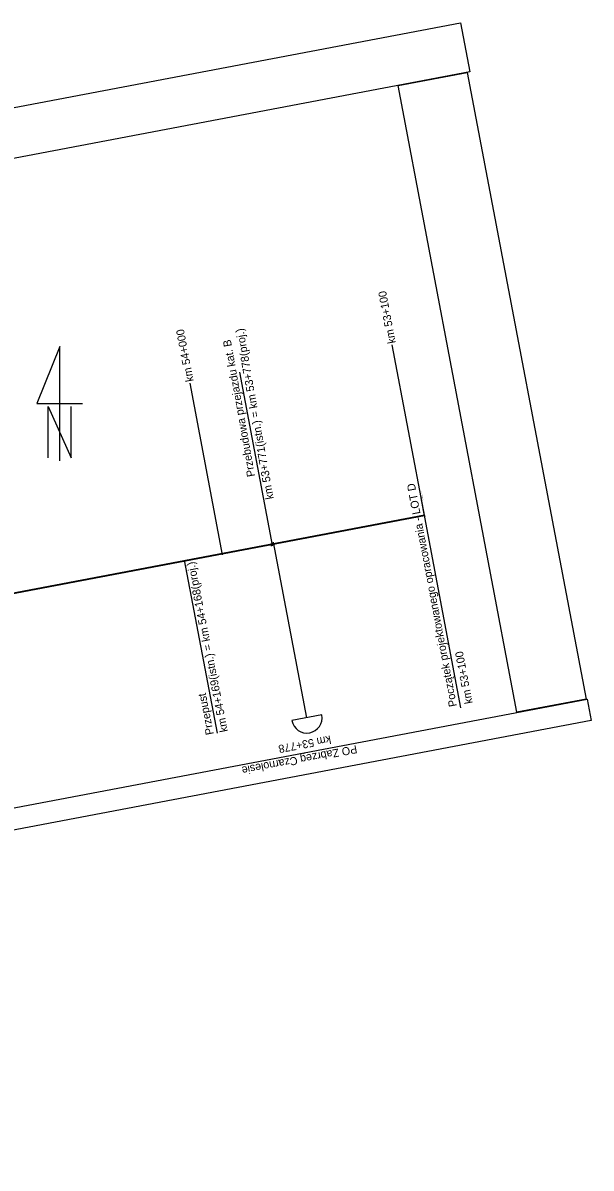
# Model space of a CAD drawing. Extents: x 6540402 to 6566579, y 5525343 to 5532423.
# Drawn here: x 6564093 to 6566579, y 5527416 to 5532423 of the extents above; entities that cross this region are included whole.
import ezdxf

# ---------------------------------------------------------------- set-up
doc = ezdxf.new("R2010")
doc.units = 0
for name, color, linetype in [('IR_default', 7, 'Continuous'), ('IR_ps_geometria', 7, 'Continuous'), ('TOR_PS_OPIS_T-hektometry projektowane', 7, 'Continuous'), ('TOR_PS_OPIS_T-opisy dodatkowe', 7, 'Continuous'), ('TOR_PS_OPIS_T-opisy glowne', 7, 'Continuous'), ('TOR_PS_P-płyty przejazdowe', 7, 'Continuous'), ('TOR_PS_T-tory projektowane', 7, 'Continuous'), ('TOR_RAMKI-ramka+tabelka 2', 7, 'Continuous')]:
    doc.layers.add(name, color=color, linetype=linetype)

msp = doc.modelspace()

# ---------------------------------------------------------------- linework, layer by layer
at = {"layer": 'DEFPOINTS'}
for points in [[(6566047.7, 5532208.3), (6558046.4, 5530690.8), (6558005.7, 5530905.3), (6566007, 5532422.8)], [(6566556.8, 5529465.9), (6566254.4, 5529408.5), (6565734.6, 5532148.9), (6566037, 5532206.3)], [(6566578.8, 5529372.7), (6556259.2, 5527415.6), (6556241.4, 5527509.5), (6566561, 5529466.6)]]:
    msp.add_lwpolyline(points, close=True, dxfattribs=at)
at = {"layer": 'IR_default'}
for p, q in [((6564204.3, 5530521), (6564204.3, 5530746)), ((6564204.3, 5530746), (6564304.3, 5530521)), ((6564304.3, 5530521), (6564304.3, 5530746))]:
    msp.add_line(p, q, dxfattribs=at)
msp.add_lwpolyline([(6564254.3, 5530508.5), (6564254.3, 5531008.5), (6564154.3, 5530758.5), (6564354.3, 5530758.5)], dxfattribs=at)
at = {"layer": 'IR_ps_geometria'}
msp.add_lwpolyline([(6565850.4, 5530267.1), (6565850.4, 5530266.9), (6565850.4, 5530266.9), (6565850.5, 5530266.9), (6565850.5, 5530266.9), (6565850.5, 5530266.9), (6565850.6, 5530266.9), (6565850.6, 5530266.8), (6565850.6, 5530266.8), (6565850.6, 5530266.8), (6565850.7, 5530266.8), (6565850.7, 5530266.8), (6565850.7, 5530266.7), (6565850.7, 5530266.7), (6565850.7, 5530266.7), (6565850.7, 5530266.6), (6565850.7, 5530266.6), (6565850.7, 5530266.6), (6565850.7, 5530266.5), (6565850.6, 5530266.5), (6565850.6, 5530266.5), (6565850.6, 5530266.5), (6565850.6, 5530266.4), (6565850.6, 5530266.4), (6565850.5, 5530266.4), (6565850.5, 5530266.4), (6565850.5, 5530266.4), (6565850.4, 5530266.4), (6565850.4, 5530266.4), (6565850.4, 5530266.4), (6565850.3, 5530266.4), (6565850.3, 5530266.4), (6565850.3, 5530266.5), (6565850.3, 5530266.5), (6565850.2, 5530266.5), (6565850.2, 5530266.5), (6565850.2, 5530266.6), (6565850.2, 5530266.6), (6565850.2, 5530266.6), (6565850.2, 5530266.7), (6565850.2, 5530266.7), (6565850.2, 5530266.7), (6565850.2, 5530266.8), (6565850.2, 5530266.8), (6565850.3, 5530266.8), (6565850.3, 5530266.8), (6565850.3, 5530266.9), (6565850.3, 5530266.9), (6565850.4, 5530266.9), (6565850.4, 5530266.9), (6565850.3, 5530267.4), (6565850.3, 5530267.4), (6565850.2, 5530267.4), (6565850.2, 5530267.4), (6565850.2, 5530267.4), (6565850.1, 5530267.4), (6565850.1, 5530267.4), (6565850.1, 5530267.4), (6565850.1, 5530267.5), (6565850, 5530267.5), (6565850, 5530267.5), (6565850, 5530267.5), (6565850, 5530267.6), (6565850, 5530267.6), (6565850, 5530267.6), (6565850, 5530267.7), (6565850, 5530267.7), (6565850, 5530267.7), (6565850.1, 5530267.8), (6565850.1, 5530267.8), (6565850.1, 5530267.8), (6565850.1, 5530267.8), (6565850.1, 5530267.9), (6565850.2, 5530267.9), (6565850.2, 5530267.9), (6565850.2, 5530267.9), (6565850.3, 5530267.9), (6565850.3, 5530267.9), (6565850.3, 5530267.9), (6565850.4, 5530267.8), (6565850.4, 5530267.8), (6565850.4, 5530267.8), (6565850.4, 5530267.8), (6565850.5, 5530267.8), (6565850.5, 5530267.7), (6565850.5, 5530267.7), (6565850.5, 5530267.7), (6565850.5, 5530267.6), (6565850.5, 5530267.6), (6565850.5, 5530267.6), (6565850.5, 5530267.5), (6565850.5, 5530267.5), (6565850.5, 5530267.5), (6565850.4, 5530267.5), (6565850.4, 5530267.4), (6565850.4, 5530267.4), (6565850.4, 5530267.4), (6565850.3, 5530267.4), (6565850.3, 5530267.4)], close=True, dxfattribs=at)
msp.add_lwpolyline([(6565850.4, 5530267.1), (6565850.4, 5530266.9), (6565850.4, 5530266.9), (6565850.5, 5530266.9), (6565850.5, 5530266.9), (6565850.5, 5530266.9), (6565850.6, 5530266.9), (6565850.6, 5530266.8), (6565850.6, 5530266.8), (6565850.6, 5530266.8), (6565850.7, 5530266.8), (6565850.7, 5530266.8), (6565850.7, 5530266.7), (6565850.7, 5530266.7), (6565850.7, 5530266.7), (6565850.7, 5530266.6), (6565850.7, 5530266.6), (6565850.7, 5530266.6), (6565850.7, 5530266.5), (6565850.6, 5530266.5), (6565850.6, 5530266.5), (6565850.6, 5530266.5), (6565850.6, 5530266.4), (6565850.6, 5530266.4), (6565850.5, 5530266.4), (6565850.5, 5530266.4), (6565850.5, 5530266.4), (6565850.4, 5530266.4), (6565850.4, 5530266.4), (6565850.4, 5530266.4), (6565850.3, 5530266.4), (6565850.3, 5530266.4), (6565850.3, 5530266.5), (6565850.3, 5530266.5), (6565850.2, 5530266.5), (6565850.2, 5530266.5), (6565850.2, 5530266.6), (6565850.2, 5530266.6), (6565850.2, 5530266.6), (6565850.2, 5530266.7), (6565850.2, 5530266.7), (6565850.2, 5530266.7), (6565850.2, 5530266.8), (6565850.2, 5530266.8), (6565850.3, 5530266.8), (6565850.3, 5530266.8), (6565850.3, 5530266.9), (6565850.3, 5530266.9), (6565850.4, 5530266.9), (6565850.4, 5530266.9), (6565850.3, 5530267.4), (6565850.3, 5530267.4), (6565850.2, 5530267.4), (6565850.2, 5530267.4), (6565850.2, 5530267.4), (6565850.1, 5530267.4), (6565850.1, 5530267.4), (6565850.1, 5530267.4), (6565850.1, 5530267.5), (6565850, 5530267.5), (6565850, 5530267.5), (6565850, 5530267.5), (6565850, 5530267.6), (6565850, 5530267.6), (6565850, 5530267.6), (6565850, 5530267.7), (6565850, 5530267.7), (6565850, 5530267.7), (6565850.1, 5530267.8), (6565850.1, 5530267.8), (6565850.1, 5530267.8), (6565850.1, 5530267.8), (6565850.1, 5530267.9), (6565850.2, 5530267.9), (6565850.2, 5530267.9), (6565850.2, 5530267.9), (6565850.3, 5530267.9), (6565850.3, 5530267.9), (6565850.3, 5530267.9), (6565850.4, 5530267.8), (6565850.4, 5530267.8), (6565850.4, 5530267.8), (6565850.4, 5530267.8), (6565850.5, 5530267.8), (6565850.5, 5530267.7), (6565850.5, 5530267.7), (6565850.5, 5530267.7), (6565850.5, 5530267.6), (6565850.5, 5530267.6), (6565850.5, 5530267.6), (6565850.5, 5530267.5), (6565850.5, 5530267.5), (6565850.5, 5530267.5), (6565850.4, 5530267.5), (6565850.4, 5530267.4), (6565850.4, 5530267.4), (6565850.4, 5530267.4), (6565850.3, 5530267.4), (6565850.3, 5530267.4)], close=True, dxfattribs=at)
msp.add_lwpolyline([(6565850.4, 5530267.1), (6565850.4, 5530266.9), (6565850.4, 5530266.9), (6565850.5, 5530266.9), (6565850.5, 5530266.9), (6565850.5, 5530266.9), (6565850.6, 5530266.9), (6565850.6, 5530266.8), (6565850.6, 5530266.8), (6565850.6, 5530266.8), (6565850.7, 5530266.8), (6565850.7, 5530266.8), (6565850.7, 5530266.7), (6565850.7, 5530266.7), (6565850.7, 5530266.7), (6565850.7, 5530266.6), (6565850.7, 5530266.6), (6565850.7, 5530266.6), (6565850.7, 5530266.5), (6565850.6, 5530266.5), (6565850.6, 5530266.5), (6565850.6, 5530266.5), (6565850.6, 5530266.4), (6565850.6, 5530266.4), (6565850.5, 5530266.4), (6565850.5, 5530266.4), (6565850.5, 5530266.4), (6565850.4, 5530266.4), (6565850.4, 5530266.4), (6565850.4, 5530266.4), (6565850.3, 5530266.4), (6565850.3, 5530266.4), (6565850.3, 5530266.5), (6565850.3, 5530266.5), (6565850.2, 5530266.5), (6565850.2, 5530266.5), (6565850.2, 5530266.6), (6565850.2, 5530266.6), (6565850.2, 5530266.6), (6565850.2, 5530266.7), (6565850.2, 5530266.7), (6565850.2, 5530266.7), (6565850.2, 5530266.8), (6565850.2, 5530266.8), (6565850.3, 5530266.8), (6565850.3, 5530266.8), (6565850.3, 5530266.9), (6565850.3, 5530266.9), (6565850.4, 5530266.9), (6565850.4, 5530266.9), (6565850.3, 5530267.4), (6565850.3, 5530267.4), (6565850.2, 5530267.4), (6565850.2, 5530267.4), (6565850.2, 5530267.4), (6565850.1, 5530267.4), (6565850.1, 5530267.4), (6565850.1, 5530267.4), (6565850.1, 5530267.5), (6565850, 5530267.5), (6565850, 5530267.5), (6565850, 5530267.5), (6565850, 5530267.6), (6565850, 5530267.6), (6565850, 5530267.6), (6565850, 5530267.7), (6565850, 5530267.7), (6565850, 5530267.7), (6565850.1, 5530267.8), (6565850.1, 5530267.8), (6565850.1, 5530267.8), (6565850.1, 5530267.8), (6565850.1, 5530267.9), (6565850.2, 5530267.9), (6565850.2, 5530267.9), (6565850.2, 5530267.9), (6565850.3, 5530267.9), (6565850.3, 5530267.9), (6565850.3, 5530267.9), (6565850.4, 5530267.8), (6565850.4, 5530267.8), (6565850.4, 5530267.8), (6565850.4, 5530267.8), (6565850.5, 5530267.8), (6565850.5, 5530267.7), (6565850.5, 5530267.7), (6565850.5, 5530267.7), (6565850.5, 5530267.6), (6565850.5, 5530267.6), (6565850.5, 5530267.6), (6565850.5, 5530267.5), (6565850.5, 5530267.5), (6565850.5, 5530267.5), (6565850.4, 5530267.5), (6565850.4, 5530267.4), (6565850.4, 5530267.4), (6565850.4, 5530267.4), (6565850.3, 5530267.4), (6565850.3, 5530267.4)], close=True, dxfattribs=at)
msp.add_lwpolyline([(6565850.4, 5530267.1), (6565850.4, 5530266.9), (6565850.4, 5530266.9), (6565850.5, 5530266.9), (6565850.5, 5530266.9), (6565850.5, 5530266.9), (6565850.6, 5530266.9), (6565850.6, 5530266.8), (6565850.6, 5530266.8), (6565850.6, 5530266.8), (6565850.7, 5530266.8), (6565850.7, 5530266.8), (6565850.7, 5530266.7), (6565850.7, 5530266.7), (6565850.7, 5530266.7), (6565850.7, 5530266.6), (6565850.7, 5530266.6), (6565850.7, 5530266.6), (6565850.7, 5530266.5), (6565850.6, 5530266.5), (6565850.6, 5530266.5), (6565850.6, 5530266.5), (6565850.6, 5530266.4), (6565850.6, 5530266.4), (6565850.5, 5530266.4), (6565850.5, 5530266.4), (6565850.5, 5530266.4), (6565850.4, 5530266.4), (6565850.4, 5530266.4), (6565850.4, 5530266.4), (6565850.3, 5530266.4), (6565850.3, 5530266.4), (6565850.3, 5530266.5), (6565850.3, 5530266.5), (6565850.2, 5530266.5), (6565850.2, 5530266.5), (6565850.2, 5530266.6), (6565850.2, 5530266.6), (6565850.2, 5530266.6), (6565850.2, 5530266.7), (6565850.2, 5530266.7), (6565850.2, 5530266.7), (6565850.2, 5530266.8), (6565850.2, 5530266.8), (6565850.3, 5530266.8), (6565850.3, 5530266.8), (6565850.3, 5530266.9), (6565850.3, 5530266.9), (6565850.4, 5530266.9), (6565850.4, 5530266.9), (6565850.3, 5530267.4), (6565850.3, 5530267.4), (6565850.2, 5530267.4), (6565850.2, 5530267.4), (6565850.2, 5530267.4), (6565850.1, 5530267.4), (6565850.1, 5530267.4), (6565850.1, 5530267.4), (6565850.1, 5530267.5), (6565850, 5530267.5), (6565850, 5530267.5), (6565850, 5530267.5), (6565850, 5530267.6), (6565850, 5530267.6), (6565850, 5530267.6), (6565850, 5530267.7), (6565850, 5530267.7), (6565850, 5530267.7), (6565850.1, 5530267.8), (6565850.1, 5530267.8), (6565850.1, 5530267.8), (6565850.1, 5530267.8), (6565850.1, 5530267.9), (6565850.2, 5530267.9), (6565850.2, 5530267.9), (6565850.2, 5530267.9), (6565850.3, 5530267.9), (6565850.3, 5530267.9), (6565850.3, 5530267.9), (6565850.4, 5530267.8), (6565850.4, 5530267.8), (6565850.4, 5530267.8), (6565850.4, 5530267.8), (6565850.5, 5530267.8), (6565850.5, 5530267.7), (6565850.5, 5530267.7), (6565850.5, 5530267.7), (6565850.5, 5530267.6), (6565850.5, 5530267.6), (6565850.5, 5530267.6), (6565850.5, 5530267.5), (6565850.5, 5530267.5), (6565850.5, 5530267.5), (6565850.4, 5530267.5), (6565850.4, 5530267.4), (6565850.4, 5530267.4), (6565850.4, 5530267.4), (6565850.3, 5530267.4), (6565850.3, 5530267.4)], close=True, dxfattribs=at)
at = {"layer": 'TOR_PS_OPIS_T-hektometry projektowane'}
for points in [[(6565851, 5530263.7), (6565708.5, 5531015.3)], [(6564966.6, 5530096.6), (6564824.2, 5530848.2)]]:
    msp.add_lwpolyline(points, dxfattribs=at)
at = {"layer": 'TOR_PS_OPIS_T-opisy dodatkowe'}
for p, q in [((6565040.6, 5530895.2), (6565184, 5530138.8)), ((6564798.9, 5530074.1), (6564942.3, 5529317.7)), ((6565400.8, 5529396.8), (6565269.7, 5529372))]:
    msp.add_line(p, q, dxfattribs=at)
msp.add_lwpolyline([(6565335.3, 5529384.4), (6565189.7, 5530152.1)], dxfattribs=at)
msp.add_arc((6565335.3, 5529384.4), 66.7, 190.7332, 10.7332, dxfattribs=at)
at = {"layer": 'TOR_PS_OPIS_T-opisy glowne'}
msp.add_lwpolyline([(6566009.3, 5529428.3), (6565851.4, 5530261.6)], dxfattribs=at)
at = {"layer": 'TOR_PS_P-płyty przejazdowe'}
for p, q in [((6565184.3, 5530145), (6565182.8, 5530140.6)), ((6565183.4, 5530142.8), (6565183.6, 5530142.8))]:
    msp.add_line(p, q, dxfattribs=at)
for points in [[(6565179, 5530137.8), (6565178.8, 5530139), (6565178.2, 5530138.9), (6565178.4, 5530137.7)], [(6565179.3, 5530139.3), (6565179.1, 5530140.6), (6565178.5, 5530140.4), (6565178.8, 5530139.2)], [(6565179.7, 5530140.8), (6565179.4, 5530142), (6565178.8, 5530141.9), (6565179.1, 5530140.7)], [(6565179.6, 5530138), (6565179.4, 5530139.1), (6565178.8, 5530139), (6565179, 5530137.8)], [(6565179.9, 5530139.4), (6565179.7, 5530140.7), (6565179.1, 5530140.6), (6565179.3, 5530139.3)], [(6565180, 5530142.2), (6565179.8, 5530143.3), (6565179.2, 5530143.2), (6565179.4, 5530142)], [(6565180.2, 5530140.9), (6565180, 5530142.1), (6565179.4, 5530142), (6565179.7, 5530140.8)], [(6565180.2, 5530138.1), (6565180, 5530139.2), (6565179.4, 5530139.1), (6565179.6, 5530138)], [(6565180.5, 5530139.5), (6565180.3, 5530140.8), (6565179.7, 5530140.7), (6565179.9, 5530139.4)], [(6565180.6, 5530142.3), (6565180.4, 5530143.4), (6565179.8, 5530143.3), (6565180, 5530142.2)], [(6565180.8, 5530141), (6565180.6, 5530142.2), (6565180, 5530142.1), (6565180.2, 5530140.9)], [(6565180.8, 5530138.2), (6565180.5, 5530139.4), (6565180, 5530139.2), (6565180.2, 5530138.1)], [(6565180.9, 5530143.7), (6565180.7, 5530145), (6565180.1, 5530144.9), (6565180.4, 5530143.6)], [(6565181.1, 5530139.6), (6565180.9, 5530140.9), (6565180.3, 5530140.8), (6565180.5, 5530139.5)], [(6565181.3, 5530145.2), (6565181, 5530146.4), (6565180.4, 5530146.3), (6565180.7, 5530145.1)], [(6565181.2, 5530142.4), (6565181, 5530143.6), (6565180.4, 5530143.4), (6565180.6, 5530142.3)], [(6565181.4, 5530138.3), (6565181.1, 5530139.5), (6565180.5, 5530139.4), (6565180.8, 5530138.2)], [(6565181.4, 5530141.2), (6565181.2, 5530142.3), (6565180.6, 5530142.2), (6565180.8, 5530141)], [(6565181.5, 5530143.8), (6565181.3, 5530145.1), (6565180.7, 5530145), (6565180.9, 5530143.7)], [(6565181.7, 5530139.7), (6565181.5, 5530141), (6565180.9, 5530140.9), (6565181.1, 5530139.6)], [(6565181.9, 5530145.4), (6565181.6, 5530146.5), (6565181, 5530146.4), (6565181.3, 5530145.2)], [(6565181.8, 5530142.5), (6565181.6, 5530143.7), (6565181, 5530143.6), (6565181.2, 5530142.4)], [(6565181.9, 5530138.4), (6565181.7, 5530139.6), (6565181.1, 5530139.5), (6565181.4, 5530138.3)], [(6565182, 5530141.3), (6565181.8, 5530142.4), (6565181.2, 5530142.3), (6565181.4, 5530141.2)], [(6565182.1, 5530143.9), (6565181.9, 5530145.2), (6565181.3, 5530145.1), (6565181.5, 5530143.8)], [(6565182.3, 5530139.8), (6565182, 5530141.1), (6565181.5, 5530141), (6565181.7, 5530139.7)], [(6565182.4, 5530145.5), (6565182.2, 5530146.6), (6565181.6, 5530146.5), (6565181.9, 5530145.4)], [(6565182.4, 5530142.6), (6565182.2, 5530143.8), (6565181.6, 5530143.7), (6565181.8, 5530142.5)], [(6565182.5, 5530138.5), (6565182.3, 5530139.7), (6565181.7, 5530139.6), (6565181.9, 5530138.4)], [(6565182.6, 5530141.4), (6565182.4, 5530142.6), (6565181.8, 5530142.4), (6565182, 5530141.3)], [(6565182.7, 5530144), (6565182.5, 5530145.3), (6565181.9, 5530145.2), (6565182.1, 5530143.9)], [(6565182.9, 5530140), (6565182.6, 5530141.2), (6565182, 5530141.1), (6565182.3, 5530139.8)], [(6565183, 5530145.6), (6565182.8, 5530146.8), (6565182.2, 5530146.6), (6565182.4, 5530145.5)], [(6565183, 5530142.7), (6565182.7, 5530143.9), (6565182.2, 5530143.8), (6565182.4, 5530142.6)], [(6565183.1, 5530138.6), (6565182.9, 5530139.8), (6565182.3, 5530139.7), (6565182.5, 5530138.5)], [(6565183.2, 5530141.5), (6565183, 5530142.7), (6565182.4, 5530142.6), (6565182.6, 5530141.4)], [(6565183.3, 5530144.2), (6565183.1, 5530145.4), (6565182.5, 5530145.3), (6565182.7, 5530144)], [(6565183.5, 5530140.1), (6565183.2, 5530141.3), (6565182.6, 5530141.2), (6565182.9, 5530140)], [(6565183.6, 5530142.8), (6565183.3, 5530144), (6565182.7, 5530143.9), (6565183, 5530142.7)], [(6565183.6, 5530145.7), (6565183.4, 5530146.9), (6565182.8, 5530146.8), (6565183, 5530145.6)], [(6565183.7, 5530138.7), (6565183.5, 5530139.9), (6565182.9, 5530139.8), (6565183.1, 5530138.6)], [(6565183.8, 5530141.6), (6565183.6, 5530142.8), (6565183, 5530142.7), (6565183.2, 5530141.5)], [(6565183.9, 5530144.3), (6565183.6, 5530145.5), (6565183.1, 5530145.4), (6565183.3, 5530144.2)], [(6565184.1, 5530140.2), (6565183.8, 5530141.5), (6565183.2, 5530141.3), (6565183.5, 5530140.1)], [(6565184.1, 5530142.9), (6565183.9, 5530144.1), (6565183.3, 5530144), (6565183.6, 5530142.8)], [(6565184.2, 5530145.8), (6565184, 5530147), (6565183.4, 5530146.9), (6565183.6, 5530145.7)], [(6565184.3, 5530138.8), (6565184.1, 5530140), (6565183.5, 5530139.9), (6565183.7, 5530138.7)], [(6565184.5, 5530144.4), (6565184.2, 5530145.7), (6565183.6, 5530145.5), (6565183.9, 5530144.3)], [(6565184.4, 5530141.7), (6565184.2, 5530142.9), (6565183.6, 5530142.8), (6565183.8, 5530141.6)], [(6565184.6, 5530140.3), (6565184.4, 5530141.6), (6565183.8, 5530141.5), (6565184.1, 5530140.2)], [(6565184.7, 5530143.1), (6565184.5, 5530144.2), (6565183.9, 5530144.1), (6565184.1, 5530142.9)], [(6565184.8, 5530145.9), (6565184.6, 5530147.1), (6565184, 5530147), (6565184.2, 5530145.8)], [(6565184.9, 5530139), (6565184.7, 5530140.1), (6565184.1, 5530140), (6565184.3, 5530138.8)], [(6565185.1, 5530144.5), (6565184.8, 5530145.8), (6565184.2, 5530145.7), (6565184.5, 5530144.4)], [(6565185, 5530141.8), (6565184.7, 5530143), (6565184.2, 5530142.9), (6565184.4, 5530141.7)], [(6565185.2, 5530140.4), (6565185, 5530141.7), (6565184.4, 5530141.6), (6565184.6, 5530140.3)], [(6565185.3, 5530143.2), (6565185.1, 5530144.3), (6565184.5, 5530144.2), (6565184.7, 5530143.1)], [(6565185.4, 5530146), (6565185.2, 5530147.2), (6565184.6, 5530147.1), (6565184.8, 5530145.9)], [(6565185.6, 5530141.9), (6565185.3, 5530143.1), (6565184.7, 5530143), (6565185, 5530141.8)], [(6565185.5, 5530139.1), (6565185.3, 5530140.3), (6565184.7, 5530140.1), (6565184.9, 5530139)], [(6565185.7, 5530144.6), (6565185.4, 5530145.9), (6565184.8, 5530145.8), (6565185.1, 5530144.5)], [(6565185.8, 5530140.5), (6565185.6, 5530141.8), (6565185, 5530141.7), (6565185.2, 5530140.4)], [(6565185.9, 5530143.3), (6565185.7, 5530144.5), (6565185.1, 5530144.3), (6565185.3, 5530143.2)], [(6565186, 5530146.1), (6565185.8, 5530147.3), (6565185.2, 5530147.2), (6565185.4, 5530146)], [(6565186.1, 5530142), (6565185.9, 5530143.2), (6565185.3, 5530143.1), (6565185.6, 5530141.9)], [(6565186.1, 5530139.2), (6565185.9, 5530140.4), (6565185.3, 5530140.3), (6565185.5, 5530139.1)], [(6565186.2, 5530144.7), (6565186, 5530146), (6565185.4, 5530145.9), (6565185.7, 5530144.6)], [(6565186.4, 5530140.6), (6565186.2, 5530141.9), (6565185.6, 5530141.8), (6565185.8, 5530140.5)], [(6565186.5, 5530143.4), (6565186.3, 5530144.6), (6565185.7, 5530144.5), (6565185.9, 5530143.3)], [(6565186.6, 5530146.2), (6565186.3, 5530147.4), (6565185.8, 5530147.3), (6565186, 5530146.1)], [(6565186.7, 5530142.2), (6565186.5, 5530143.3), (6565185.9, 5530143.2), (6565186.1, 5530142)], [(6565186.7, 5530139.3), (6565186.4, 5530140.5), (6565185.9, 5530140.4), (6565186.1, 5530139.2)], [(6565186.8, 5530144.8), (6565186.6, 5530146.1), (6565186, 5530146), (6565186.2, 5530144.7)], [(6565187, 5530140.7), (6565186.8, 5530142), (6565186.2, 5530141.9), (6565186.4, 5530140.6)], [(6565187.2, 5530146.4), (6565186.9, 5530147.5), (6565186.3, 5530147.4), (6565186.6, 5530146.2)], [(6565187.1, 5530143.5), (6565186.9, 5530144.7), (6565186.3, 5530144.6), (6565186.5, 5530143.4)], [(6565187.3, 5530142.3), (6565187.1, 5530143.4), (6565186.5, 5530143.3), (6565186.7, 5530142.2)], [(6565187.4, 5530144.9), (6565187.2, 5530146.2), (6565186.6, 5530146.1), (6565186.8, 5530144.8)], [(6565187.7, 5530146.5), (6565187.5, 5530147.7), (6565186.9, 5530147.5), (6565187.2, 5530146.4)], [(6565187.7, 5530143.6), (6565187.5, 5530144.8), (6565186.9, 5530144.7), (6565187.1, 5530143.5)], [(6565187.9, 5530142.4), (6565187.7, 5530143.6), (6565187.1, 5530143.4), (6565187.3, 5530142.3)], [(6565188, 5530145), (6565187.8, 5530146.3), (6565187.2, 5530146.2), (6565187.4, 5530144.9)], [(6565188.3, 5530146.6), (6565188.1, 5530147.8), (6565187.5, 5530147.7), (6565187.7, 5530146.5)], [(6565188.3, 5530143.7), (6565188, 5530144.9), (6565187.5, 5530144.8), (6565187.7, 5530143.6)], [(6565188.6, 5530145.2), (6565188.4, 5530146.4), (6565187.8, 5530146.3), (6565188, 5530145)], [(6565188.9, 5530146.7), (6565188.7, 5530147.9), (6565188.1, 5530147.8), (6565188.3, 5530146.6)]]:
    msp.add_lwpolyline(points, close=True, dxfattribs=at)
at = {"layer": 'TOR_PS_T-tory projektowane'}
for p, q in [((6565849.6, 5530271.1), (6560351.9, 5529229)), ((6565850.4, 5530267.1), (6560937.8, 5529336))]:
    msp.add_line(p, q, dxfattribs=at)
at = {"layer": 'TOR_RAMKI-ramka+tabelka 2'}
msp.add_line((6565850.4, 5530267.1), (6565835.5, 5530345.7), dxfattribs=at)

# ---------------------------------------------------------------- texts
at = {"layer": 'TOR_PS_OPIS_T-hektometry projektowane'}
for s, p in [('km 53+100', (6565724.6, 5531024.3)), ('km 54+000', (6564840.3, 5530857.2)), ('Początek projektowanego opracowania - LOT D', (6565992, 5529435.9)), ('km 53+100', (6566060.8, 5529448.9))]:
    msp.add_text(s, height=35, rotation=100.7332, dxfattribs=at).set_placement(p)
at = {"layer": 'TOR_PS_OPIS_T-opisy dodatkowe'}
for s, rotation, p in [('km 53+771(istn.) = km 53+778(proj.)', 100.1117, (6565190.4, 5530342.9)), ('Przebudowa przejazdu kat. B', 100.1117, (6565108.9, 5530441.1)), ('km 54+169(istn.) = km 54+168(proj.)', 101.1578, (6564990.2, 5529325.4)), ('Przepust', 101.1578, (6564928.4, 5529313.2)), ('km 53+778', 190.7332, (6565437.3, 5529307.5)), ('PO Zabrzeg Czarnolesie', 190.7332, (6565551.6, 5529265.1))]:
    msp.add_text(s, height=35, rotation=rotation, dxfattribs=at).set_placement(p)
at = {"layer": 'TOR_RAMKI-ramka+tabelka 2'}
for s, p in [('POCZĄTEK OPRACOWANIA', (6565836.2, 5530374.2)), ('KM 53+100,00', (6565835.5, 5530359.6))]:
    msp.add_text(s, height=2, rotation=280.7332, dxfattribs=at).set_placement(p)

doc.saveas('drawing.dxf')
